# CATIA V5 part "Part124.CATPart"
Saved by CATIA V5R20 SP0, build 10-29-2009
Part number: IA 4717SF
Revision: ANY
Definition: UNKNOWN
Nomenclature: IA 4717SF
Source: Unknown
Bounding box of the stored display mesh (mm): x -2.35 to 2.35, y -7.925 to 9.045, z -2.35 to 2.35
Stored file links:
  C:\Users\Utente\Desktop\IO LAVORO\3D X SITO CF\CUMSA\3D files FA\FA 084705-20\Part124.CATPart

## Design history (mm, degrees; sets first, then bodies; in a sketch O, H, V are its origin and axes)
Body1 "Cortar-Extruir2" (main body)
  Solid1: solid without history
